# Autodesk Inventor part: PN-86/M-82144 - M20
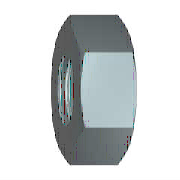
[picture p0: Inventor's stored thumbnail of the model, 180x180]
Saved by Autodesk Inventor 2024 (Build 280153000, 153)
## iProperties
Company: ATC
Created: 2023-03
Part Number: PN-86/M-82144 - M20
Material: Stal, miękka
Description: Nakrętka
Document SubType Name: Modeling
Standard: PN-86/M-82144
Designer: Andrzej Jaskulski
Standards Organization: PN
Language: pl-PL
Size Designation: M20
Categories: <MemberInstance><Categories><Category DisplayName="Mocowania" InternalName="e4da775c-781d-43d5-af7c-5136215cf5a6" Mnemonic="FSTN"><Category DisplayName="Nakrętk
Density: 7.85 g/cm^3
Appearance: Częściowo polerowany
Checked By: A.J.
Engr Approved By: Andrzej Jaskulski
Mfg Approved By: Andrzej Jaskulski
Authority: A.J.
IsCustomPart: 0
Author: Andrzej Jaskulski
Title: A.J.: Kurs R2024-MEP
Revision Number: 1/24
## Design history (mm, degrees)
workaxis "Work Axis1"
workplane "Work Plane1"
sketch "Szkic1"
  geometry: L1 (-17.321, 0)-(-8.66, 15); L2 (-8.66, 15)-(8.66, 15); L3 (8.66, 15)-(17.321, 0); L4 (17.321, 0)-(8.66, -15); L5 (8.66, -15)-(-8.66, -15); L6 (-8.66, -15)-(-17.321, 0); 2 further points
  constraints: 12 end point, 1 coincident, 1 horizontal, 11 other
  dimensions: "d0" = 34.64102 distance of L3.end L1.start (= 1.1547 x SW)
extrude "Bryła" new body sketch "Szkic1" distance "d1" = 18 (= KOH); taper "d2" = 0 deg
revolve "Faza1" stored, may be unused: angle "d7" = 90 deg
sketch "Szkic3"
  geometry: A1 r 15 centre (0, 0) between (-7.5, -12.99) and (7.5, -12.99) reference; 1 further point
  constraints: 1 coincident
hole "Gwint" sketch "Szkic3" diameter "d25" = 17.294; stored, may be unused: countersink angle "d29" = 82 deg, drill point angle "d31" = 118 deg; dims "d26" = 6, "d27" = 4, "d28" = 2, "d30" = 8
body "Solid1"
chamfer "Faza2" distance "d8" = 1.35316 (= -0.5 x GD1 + 0.5 x NND); stored, may be unused: angle "d9" = 30 deg, second distance "d40" = 1.35316 (= -0.5 x GD1 + 0.5 x NND)
chamfer "Faza3" distance "d10" = 1.35316 (= -0.5 x GD1 + 0.5 x NND); stored, may be unused: angle "d11" = 30 deg, second distance "d41" = 1.35316 (= -0.5 x GD1 + 0.5 x NND)
sketch "Szkic2"
  geometry: L1 (0, 8.66)-(0, 17.321) reference; L2 (0, 17.321)-(18, 17.321) reference; L3 (18, 8.66)-(18, 17.321) reference; L4 (-3.6, 0)-(21.6, 0) reference; L5 (1.34, 17.321)-(0, 15); L6 (16.66, 17.321)-(18, 15)
  constraints: 4 end point, 4 point on line
  dimensions: "d3" = 30 deg angle of L1 L5 (= ANG1); "d4" = 30 deg angle of L3 L6 (= ANG2); "d5" = 30 diameter of L5.end L4 (= SW0); "d6" = 30 diameter of L6.end L4 (= SW01)
other parameters: "ANG1" = 30 deg [user parameter; used in 1 equation term], "ANG2" = 30 deg [user parameter; used in 1 equation term], "KOH" = 18 [user parameter; used in 1 equation term], "SW0" = 30 (= SW) [user parameter; used in 1 equation term], "SW01" = 30 (= SW) [user parameter; used in 1 equation term], "GD1" = 17.29367 (computed from THREADDIA, PTC, TOA) [user parameter; used in 4 equation terms], "d13" = 0, "d14" = 0, "d39" = 0, "d42" = 0, "GUL" = 1.35317 (= 0.541266 x PTC) [user parameter], "TPU" = 4 (computed from PTC) [user parameter], "TOA" = 30 deg [user parameter; used in 1 equation term], "PTC" = 2.5 [user parameter; used in 4 equation terms], "E0" = 34.65 (= 1.155 x SW) [user parameter], "GAL" = 1.35317 (= 0.541266 x PTC) [user parameter]
